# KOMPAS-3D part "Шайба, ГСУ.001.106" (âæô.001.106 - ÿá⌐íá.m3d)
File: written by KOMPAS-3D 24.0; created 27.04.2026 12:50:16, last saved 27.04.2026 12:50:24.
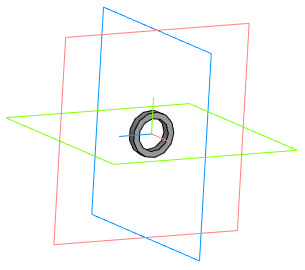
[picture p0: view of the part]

Document properties: Автор: User7; Полное имя файла: C:\Users\User7\Desktop\олимп\ГСУ.001.106 - Шайба.m3d

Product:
- Part/product: Шайба  | designation ГСУ.001.106
    Масса: 0.000703

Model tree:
1. Эскиз:1
2. Элемент выдавливания:1
     Расстояние 1 = 2

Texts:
  ГСУ.001.106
